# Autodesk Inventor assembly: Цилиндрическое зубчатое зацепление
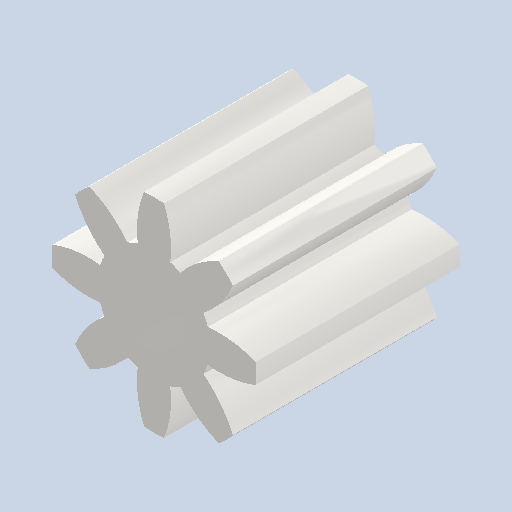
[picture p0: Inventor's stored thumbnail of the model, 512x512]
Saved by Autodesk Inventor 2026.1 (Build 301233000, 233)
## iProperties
ClientObjectVersion: 1
Created: 2026-02
Part Number: Цилиндрическое зубчатое зацепление
Document SubType Name: Assembly
Designer: Yury Melnikov
Categories: <?xml version="1.0" encoding="UTF-16"?> <MemberInstance><Categories><FamilyTemplate/><ParamToTemplateMap><ParamToTemplate><ParamToTemplate CategoryParameter="//
Author: Yury Melnikov
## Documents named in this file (2)
- C:\Users\user\Documents\Проекты\ВсОШ_РОБО\Робот V2\Шестеренки ось Х\Мастер проектирования\Цилиндрическое зубчатое зацепление1.iam
- C:\Users\user\Documents\Проекты\ВсОШ_РОБО\Робот V2\Шестеренки ось Х\Мастер проектирования\Цилиндрическое зубчатое зацепление11.ipt
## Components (1 placed, 1 different names)
1. Цилиндрическое зубчатое зацепление1:1
